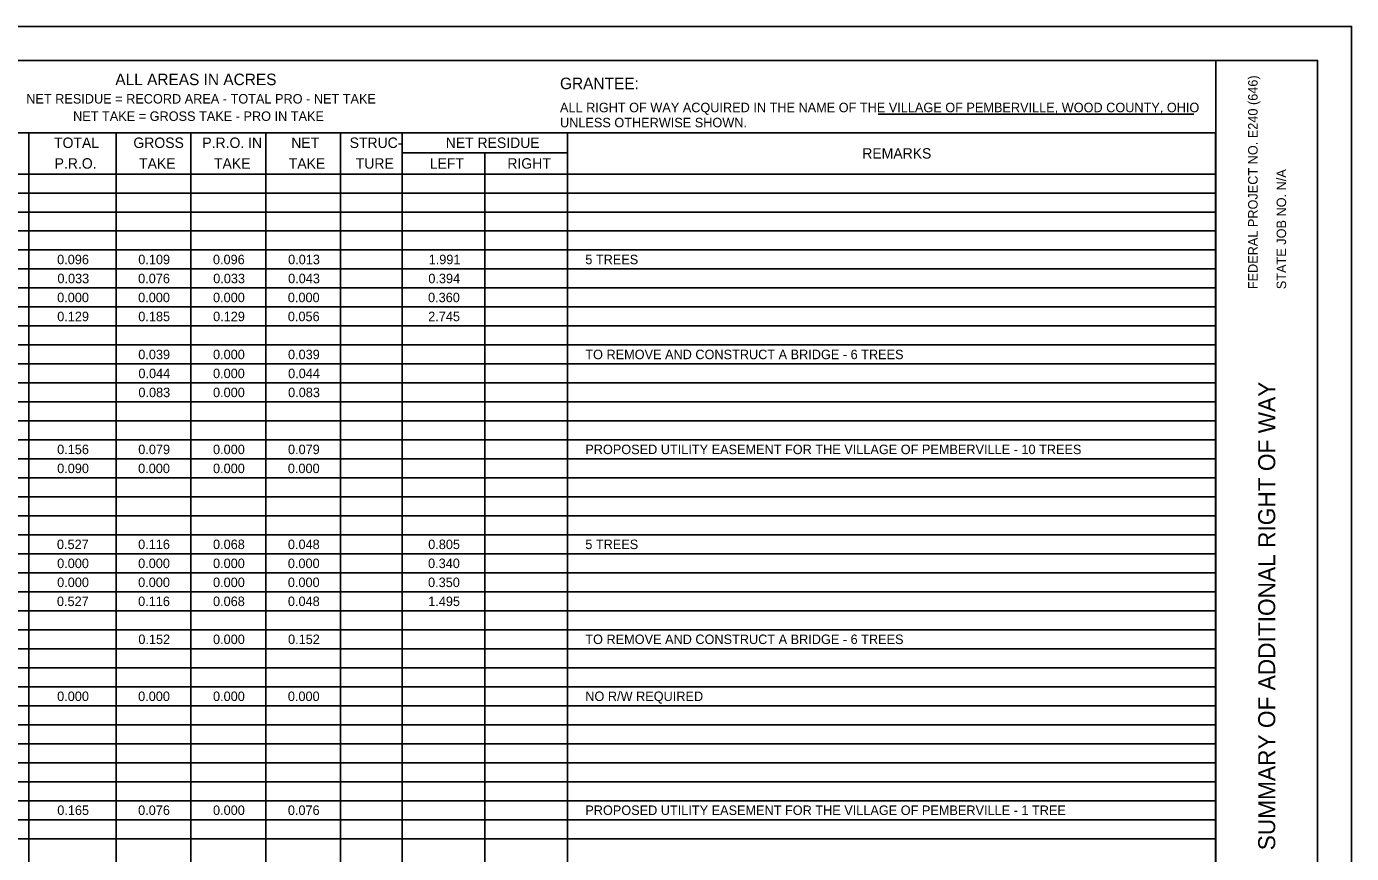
# Model space of a CAD drawing. Extents: x 0 to 34, y 0 to 22.
# Drawn here: x 14.47 to 34, y 9.81 to 22 of the extents above; entities that cross this region are included whole.
import ezdxf

# ---------------------------------------------------------------- set-up
doc = ezdxf.new("R2010")
doc.units = 0
for name, color, linetype in [('SH_Border', 7, 'Continuous'), ('SH_Cut_Line', 7, 'Continuous'), ('SH_Data', 7, 'Continuous'), ('SH_Text', 7, 'Continuous')]:
    doc.layers.add(name, color=color, linetype=linetype)

msp = doc.modelspace()

# ---------------------------------------------------------------- linework, layer by layer
at = {"layer": 'SH_Border'}
for p, q in [((32, 0.5), (32, 21.5)), ((1.507, 20.434), (31.995, 20.434)), ((14.503, 20.434), (14.503, 3.865)), ((15.787, 20.434), (15.787, 3.865)), ((16.891, 20.434), (16.891, 3.865)), ((17.995, 20.434), (17.995, 3.865)), ((19.098, 20.434), (19.098, 3.865)), ((20.004, 20.434), (20.004, 3.865)), ((22.442, 20.434), (22.442, 3.865)), ((31.995, 20.434), (31.995, 3.865)), ((20.004, 20.138), (22.442, 20.138)), ((21.223, 20.138), (21.223, 3.865)), ((1.507, 19.825), (31.995, 19.825)), ((1.507, 19.545), (31.995, 19.545)), ((1.507, 19.265), (31.995, 19.265)), ((1.507, 18.985), (31.995, 18.985)), ((1.507, 18.705), (31.995, 18.705)), ((1.507, 18.425), (31.995, 18.425)), ((1.507, 18.145), (31.995, 18.145)), ((13.366, 17.865), (19.098, 17.865)), ((19.098, 17.865), (20.004, 17.865)), ((20.004, 17.865), (22.442, 17.865)), ((22.442, 17.865), (31.995, 17.865)), ((1.507, 17.585), (31.995, 17.585)), ((1.507, 17.305), (31.995, 17.305)), ((1.507, 17.025), (31.995, 17.025)), ((1.507, 16.745), (15.787, 16.745)), ((15.787, 16.745), (19.098, 16.745)), ((19.098, 16.745), (31.995, 16.745)), ((1.507, 16.465), (31.995, 16.465)), ((1.507, 16.185), (31.995, 16.185)), ((1.507, 15.905), (31.995, 15.905)), ((1.507, 15.625), (31.995, 15.625)), ((1.507, 15.345), (31.995, 15.345)), ((1.507, 15.065), (31.995, 15.065)), ((1.507, 14.785), (31.995, 14.785)), ((1.507, 14.505), (31.995, 14.505)), ((1.507, 14.225), (31.995, 14.225)), ((1.507, 13.945), (31.995, 13.945)), ((13.366, 13.665), (19.098, 13.665)), ((19.098, 13.665), (20.004, 13.665)), ((20.004, 13.665), (21.223, 13.665)), ((21.223, 13.665), (31.995, 13.665)), ((1.507, 13.385), (31.995, 13.385)), ((1.507, 13.105), (31.995, 13.105)), ((1.507, 12.825), (31.995, 12.825)), ((1.507, 12.545), (31.995, 12.545)), ((1.507, 12.265), (31.995, 12.265)), ((1.507, 11.985), (31.995, 11.985)), ((1.507, 11.705), (31.995, 11.705)), ((1.507, 11.425), (31.995, 11.425)), ((1.507, 11.145), (31.995, 11.145)), ((1.507, 10.865), (31.995, 10.865)), ((1.507, 10.585), (31.995, 10.585)), ((1.507, 10.305), (31.995, 10.305)), ((1.507, 10.025), (31.995, 10.025))]:
    msp.add_line(p, q, dxfattribs=at)
msp.add_lwpolyline([(1.5, 21.5), (33.5, 21.5), (33.5, 0.5), (1.5, 0.5)], close=True, dxfattribs=at)
at = {"layer": 'SH_Cut_Line'}
msp.add_lwpolyline([(0, 0), (34, 0), (34, 22), (0, 22)], close=True, dxfattribs=at)
at = {"layer": 'SH_Text'}
for p, q in [((27.024, 20.706), (31.678, 20.706)), ((1.507, 20.434), (32, 20.434))]:
    msp.add_line(p, q, dxfattribs=at)

# ---------------------------------------------------------------- texts
at = {"layer": 'SH_Data'}
msp.add_text('SUMMARY OF ADDITIONAL RIGHT OF WAY', height=0.25, rotation=90, dxfattribs=at).set_placement((32.875, 9.854))
at = {"layer": 'SH_Text'}
for s, height, p in [('ALL AREAS IN ACRES', 0.17, (15.777, 21.135)), ('GRANTEE:', 0.17, (22.332, 21.076)), ('NET RESIDUE = RECORD AREA - TOTAL PRO - NET TAKE', 0.14, (14.464, 20.864)), ('NET TAKE = GROSS TAKE - PRO IN TAKE', 0.14, (15.154, 20.608)), ('ALL RIGHT OF WAY ACQUIRED IN THE NAME OF THE VILLAGE OF PEMBERVILLE, WOOD COUNTY, OHIO', 0.14, (22.332, 20.736)), ('UNLESS OTHERWISE SHOWN.', 0.14, (22.332, 20.514)), ('TOTAL', 0.154, (14.873, 20.209)), ('GROSS', 0.154, (16.043, 20.209)), ('P.R.O. IN', 0.154, (17.059, 20.209)), ('NET', 0.154, (18.37, 20.209)), ('STRUC-', 0.154, (19.231, 20.209)), ('NET RESIDUE', 0.154, (20.647, 20.209)), ('REMARKS', 0.154, (26.788, 20.052)), ('P.R.O.', 0.154, (14.882, 19.904)), ('TAKE', 0.154, (16.127, 19.904)), ('TAKE', 0.154, (17.231, 19.904)), ('TAKE', 0.154, (18.334, 19.904)), ('TURE', 0.154, (19.321, 19.904)), ('LEFT', 0.154, (20.412, 19.904)), ('RIGHT', 0.154, (21.556, 19.904)), ('0.096', 0.14, (14.919, 18.495)), ('0.109', 0.14, (16.115, 18.495)), ('0.096', 0.14, (17.216, 18.495)), ('0.013', 0.14, (18.324, 18.495)), ('1.991', 0.14, (20.396, 18.495)), ('5 TREES', 0.14, (22.705, 18.495)), ('0.033', 0.14, (14.923, 18.215)), ('0.076', 0.14, (16.113, 18.215)), ('0.033', 0.14, (17.22, 18.215)), ('0.043', 0.14, (18.324, 18.215)), ('0.394', 0.14, (20.391, 18.215)), ('0.000', 0.14, (14.919, 17.935)), ('0.000', 0.14, (16.113, 17.935)), ('0.000', 0.14, (17.217, 17.935)), ('0.000', 0.14, (18.32, 17.935)), ('0.360', 0.14, (20.387, 17.935)), ('0.129', 0.14, (14.92, 17.655)), ('0.185', 0.14, (16.115, 17.655)), ('0.129', 0.14, (17.218, 17.655)), ('0.056', 0.14, (18.32, 17.655)), ('2.745', 0.14, (20.389, 17.655)), ('0.039', 0.14, (16.115, 17.095)), ('0.000', 0.14, (17.217, 17.095)), ('0.039', 0.14, (18.322, 17.095)), ('TO REMOVE AND CONSTRUCT A BRIDGE - 6 TREES', 0.14, (22.705, 17.095)), ('0.044', 0.14, (16.117, 16.815)), ('0.000', 0.14, (17.217, 16.815)), ('0.044', 0.14, (18.324, 16.815)), ('0.083', 0.14, (16.117, 16.535)), ('0.000', 0.14, (17.217, 16.535)), ('0.083', 0.14, (18.324, 16.535)), ('0.156', 0.14, (14.919, 15.695)), ('0.079', 0.14, (16.115, 15.695)), ('0.000', 0.14, (17.217, 15.695)), ('0.079', 0.14, (18.322, 15.695)), ('PROPOSED UTILITY EASEMENT FOR THE VILLAGE OF PEMBERVILLE - 10 TREES', 0.14, (22.705, 15.695)), ('0.090', 0.14, (14.919, 15.415)), ('0.000', 0.14, (16.113, 15.415)), ('0.000', 0.14, (17.217, 15.415)), ('0.000', 0.14, (18.32, 15.415)), ('0.527', 0.14, (14.916, 14.295)), ('0.116', 0.14, (16.113, 14.295)), ('0.068', 0.14, (17.217, 14.295)), ('0.048', 0.14, (18.321, 14.295)), ('0.805', 0.14, (20.389, 14.295)), ('5 TREES', 0.14, (22.705, 14.295)), ('0.000', 0.14, (14.919, 14.015)), ('0.000', 0.14, (16.113, 14.015)), ('0.000', 0.14, (17.217, 14.015)), ('0.000', 0.14, (18.32, 14.015)), ('0.340', 0.14, (20.387, 14.015)), ('0.000', 0.14, (14.919, 13.735)), ('0.000', 0.14, (16.113, 13.735)), ('0.000', 0.14, (17.217, 13.735)), ('0.000', 0.14, (18.32, 13.735)), ('0.350', 0.14, (20.387, 13.735)), ('0.527', 0.14, (14.916, 13.455)), ('0.116', 0.14, (16.113, 13.455)), ('0.068', 0.14, (17.217, 13.455)), ('0.048', 0.14, (18.321, 13.455)), ('1.495', 0.14, (20.389, 13.455)), ('0.152', 0.14, (16.116, 12.895)), ('0.000', 0.14, (17.217, 12.895)), ('0.152', 0.14, (18.323, 12.895)), ('TO REMOVE AND CONSTRUCT A BRIDGE - 6 TREES', 0.14, (22.705, 12.895)), ('0.000', 0.14, (14.919, 12.055)), ('0.000', 0.14, (16.113, 12.055)), ('0.000', 0.14, (17.217, 12.055)), ('0.000', 0.14, (18.32, 12.055)), ('NO R/W REQUIRED', 0.14, (22.705, 12.055)), ('0.165', 0.14, (14.921, 10.375)), ('0.076', 0.14, (16.113, 10.375)), ('0.000', 0.14, (17.217, 10.375)), ('0.076', 0.14, (18.32, 10.375)), ('PROPOSED UTILITY EASEMENT FOR THE VILLAGE OF PEMBERVILLE - 1 TREE', 0.14, (22.705, 10.375))]:
    msp.add_text(s, height=height, dxfattribs=at).set_placement(p)
for s, p in [('FEDERAL PROJECT NO. E240 (646)', (32.616, 18.127)), ('STATE JOB NO. N/A', (33.036, 18.127))]:
    msp.add_text(s, height=0.14, rotation=90, dxfattribs=at).set_placement(p)

doc.saveas('drawing.dxf')
